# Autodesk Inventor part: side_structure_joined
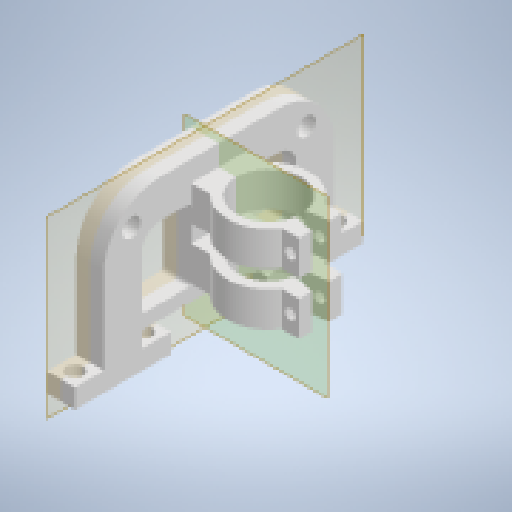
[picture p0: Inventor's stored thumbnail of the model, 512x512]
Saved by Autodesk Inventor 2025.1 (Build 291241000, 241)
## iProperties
Created: 2024-12
Part Number: side_structure_joined
Material: Generic
Document SubType Name: Modeling
Designer: mansa
Density: 1 g/cm^3
Appearance: Default
Author: mansa
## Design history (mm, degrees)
derived "joining assembly.iam"
workplane "Work Plane1"
workplane "Work Plane2"
body "Solid1"
node "side_structure_final_v2.ipt:1"
node "motor holder_sideways_v1.ipt:1"
node "motor holder_tighter.ipt:1"
node "joining assembly.iam_Bodies"
